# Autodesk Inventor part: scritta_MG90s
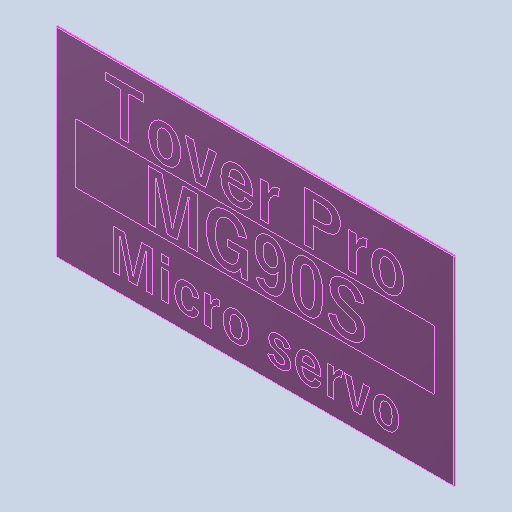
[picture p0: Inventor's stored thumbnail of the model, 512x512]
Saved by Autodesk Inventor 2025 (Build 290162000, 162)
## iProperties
Created: 2018-08
Part Number: scritta_MG90s
Material: Plastica PAEK
Document SubType Name: Modeling
Designer: Ryzen5700u
Density: 1.32 g/cm^3
Appearance: Default
Author: Ryzen5700u
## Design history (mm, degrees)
feature "Solido1"
node "Solido2"
